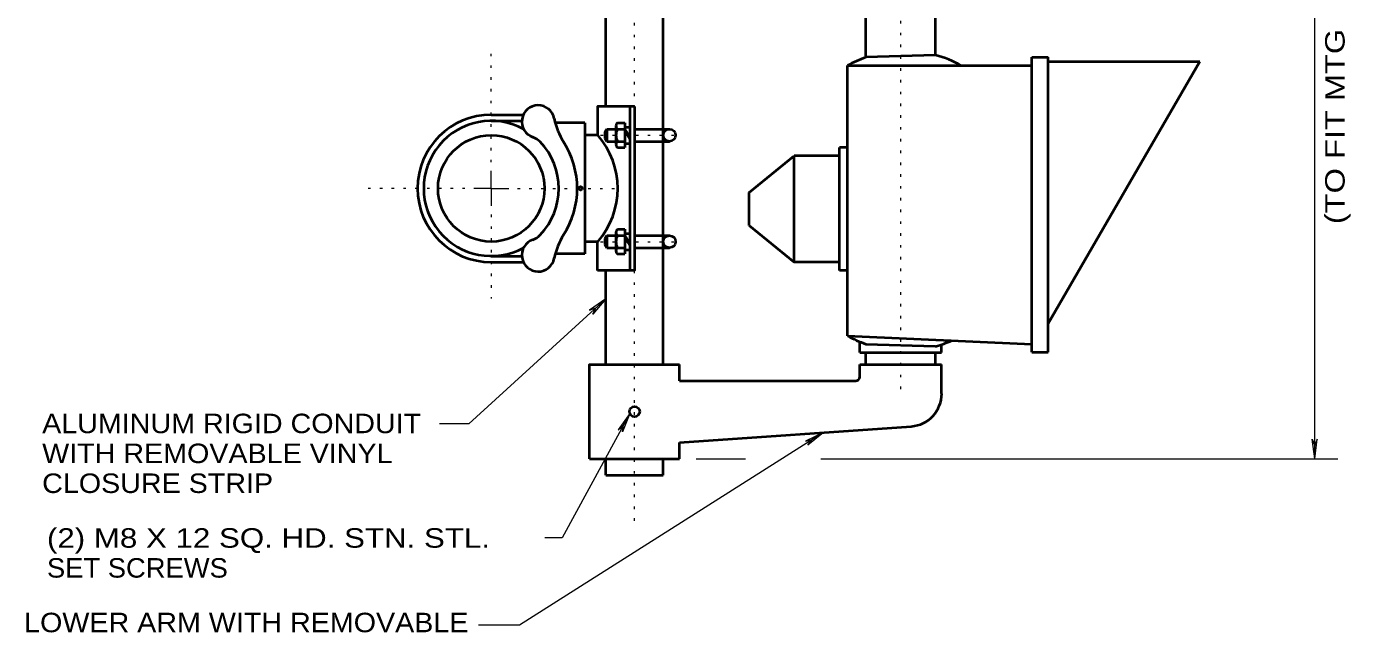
# Model space of a CAD drawing. Extents: x 312583 to 312854, y 144419 to 144597.
# Drawn here: x 312717.4 to 312769, y 144455.6 to 144479.3 of the extents above; entities that cross this region are included whole.
import ezdxf

# ---------------------------------------------------------------- set-up
doc = ezdxf.new("R2010")
doc.units = 0
doc.header["$LTSCALE"] = 0.3
doc.linetypes.add('DOTTED', pattern=[1.5, 0.3, -1.2])
doc.layers.add('1', color=7, linetype='Continuous', lineweight=40)
doc.layers.add('2', color=7, linetype='Continuous', lineweight=40)

msp = doc.modelspace()

# ---------------------------------------------------------------- linework, layer by layer
at = {"layer": '1', "linetype": 'DOTTED', "lineweight": 13}
for p, q in [((312741.0994, 144459.9829), (312741.0994, 144511.0659)), ((312751.4801, 144465.1195), (312751.4801, 144507.1559)), ((312739.7731, 144475.0249), (312742.9854, 144475.0249)), ((312739.7731, 144470.8695), (312742.8858, 144470.8695))]:
    msp.add_line(p, q, dxfattribs=at)
at = {"layer": '1'}
for p, q in [((312742.2188, 144466.0779), (312742.2188, 144506.0059)), ((312739.9801, 144476.1442), (312739.9801, 144486.0419)), ((312750.1231, 144478.0609), (312750.1231, 144480.1845)), ((312752.8371, 144478.1452), (312752.8371, 144480.1002)), ((312752.8371, 144478.1452), (312750.1231, 144478.0609)), ((312756.5938, 144466.5609), (312756.5938, 144478.0609)), ((312756.5938, 144478.0609), (312757.2301, 144478.0609)), ((312757.2301, 144466.5609), (312757.2301, 144478.0609)), ((312757.2301, 144477.8999), (312763.1411, 144477.8999)), ((312757.2301, 144467.6725), (312763.1411, 144477.8999)), ((312749.4024, 144477.7389), (312756.5938, 144477.7389)), ((312749.4024, 144467.1972), (312749.4024, 144477.7389)), ((312735.5104, 144475.8222), (312736.7601, 144475.8222)), ((312735.5104, 144475.5845), (312736.6988, 144475.5845)), ((312739.1521, 144475.5002), (312738.0021, 144475.5002)), ((312739.1521, 144475.5002), (312739.1521, 144470.3942)), ((312740.3711, 144475.3852), (312740.3711, 144474.6569)), ((312740.4324, 144475.5002), (312740.7238, 144475.5002)), ((312740.7238, 144475.5002), (312740.7238, 144474.5419)), ((312740.7238, 144475.3392), (312740.9078, 144475.3392)), ((312740.9078, 144475.3392), (312740.9078, 144474.7029)), ((312739.6581, 144475.0249), (312739.1521, 144475.0249)), ((312739.9418, 144475.1399), (312740.0108, 144475.2625)), ((312739.9418, 144475.1399), (312739.9418, 144474.9099)), ((312739.9418, 144474.9099), (312740.0108, 144474.7795)), ((312740.0108, 144475.2625), (312740.0108, 144474.7795)), ((312740.0108, 144475.2625), (312740.3711, 144475.2625)), ((312740.4324, 144475.2625), (312740.7238, 144475.2625)), ((312740.7238, 144475.2625), (312740.9078, 144474.9482)), ((312740.7238, 144475.2012), (312740.9078, 144474.8792)), ((312741.0994, 144475.2625), (312742.4564, 144475.2625)), ((312740.0108, 144474.7795), (312740.3711, 144474.7795)), ((312740.4324, 144474.7795), (312740.7238, 144474.7795)), ((312740.4324, 144474.5419), (312740.7238, 144474.5419)), ((312740.7238, 144474.7029), (312740.9078, 144474.7029)), ((312741.0994, 144474.7795), (312742.4564, 144474.7795)), ((312749.0881, 144469.7502), (312749.0881, 144474.5419)), ((312749.4024, 144474.5419), (312749.0881, 144474.5419)), ((312745.5691, 144472.7862), (312747.3248, 144474.2199)), ((312747.3248, 144470.0722), (312747.3248, 144474.2199)), ((312749.0881, 144474.2199), (312747.3248, 144474.2199)), ((312745.5691, 144471.5059), (312745.5691, 144472.7862)), ((312740.3711, 144471.2299), (312740.3711, 144470.5092)), ((312740.4324, 144471.3525), (312740.7238, 144471.3525)), ((312740.7238, 144471.3525), (312740.7238, 144470.3942)), ((312740.7238, 144471.1915), (312740.9078, 144471.1915)), ((312740.9078, 144471.1915), (312740.9078, 144470.5475)), ((312745.5691, 144471.5059), (312747.3248, 144470.0722)), ((312739.6581, 144470.8695), (312739.1521, 144470.8695)), ((312739.6581, 144469.7502), (312739.6581, 144470.8695)), ((312739.9418, 144470.9845), (312740.0108, 144471.1072)), ((312739.9418, 144470.9845), (312739.9418, 144470.7545)), ((312739.9418, 144470.7545), (312740.0108, 144470.6319)), ((312740.0108, 144471.1072), (312740.0108, 144470.6319)), ((312740.0108, 144471.1072), (312740.3711, 144471.1072)), ((312740.4324, 144471.1072), (312740.7238, 144471.1072)), ((312740.7238, 144471.1072), (312740.9078, 144470.7929)), ((312740.7238, 144471.0459), (312740.9078, 144470.7315)), ((312741.0994, 144471.1072), (312742.4564, 144471.1072)), ((312735.5104, 144470.3099), (312736.6988, 144470.3099)), ((312739.1521, 144470.3942), (312738.0021, 144470.3942)), ((312740.0108, 144470.6319), (312740.3711, 144470.6319)), ((312740.4324, 144470.6319), (312740.7238, 144470.6319)), ((312740.4324, 144470.3942), (312740.7238, 144470.3942)), ((312740.7238, 144470.5475), (312740.9078, 144470.5475)), ((312741.0994, 144470.6319), (312742.4564, 144470.6319)), ((312735.5104, 144470.0722), (312736.7601, 144470.0722)), ((312739.9801, 144466.0779), (312739.9801, 144469.7502)), ((312749.0881, 144470.0722), (312747.3248, 144470.0722)), ((312749.4024, 144469.7502), (312749.0881, 144469.7502)), ((312749.4024, 144467.1972), (312756.5938, 144466.8752)), ((312749.8854, 144466.5532), (312749.8854, 144466.9672)), ((312749.8854, 144466.5532), (312753.0748, 144466.5532)), ((312750.1231, 144466.8752), (312752.8371, 144466.7909)), ((312750.1231, 144466.0779), (312750.1231, 144466.5532)), ((312752.8371, 144466.0779), (312752.8371, 144466.5532)), ((312753.0748, 144466.5532), (312753.0748, 144466.8599)), ((312756.5938, 144466.5609), (312757.2301, 144466.5609)), ((312742.8551, 144465.4415), (312742.8551, 144466.0779)), ((312749.8854, 144465.6025), (312749.8854, 144466.0779)), ((312749.8854, 144466.0779), (312753.0748, 144466.0779)), ((312753.0748, 144464.9432), (312753.0748, 144466.0779)), ((312742.8551, 144465.4415), (312749.7244, 144465.4415)), ((312742.8551, 144463.0419), (312751.8864, 144463.6629)), ((312742.8551, 144462.4055), (312742.8551, 144463.0419)), ((312739.3438, 144462.4055), (312742.8551, 144462.4055)), ((312739.9801, 144461.7692), (312739.9801, 144462.4055)), ((312742.2188, 144461.7692), (312742.2188, 144462.4055)), ((312739.9801, 144461.7692), (312742.2188, 144461.7692))]:
    msp.add_line(p, q, dxfattribs=at)
for points in [[(312741.0994, 144476.1442), (312741.0994, 144469.7502), (312739.6581, 144469.7502)], [(312741.0994, 144476.1442), (312739.6581, 144476.1442), (312739.6581, 144475.0249)], [(312741.0994, 144476.1442), (312740.9078, 144476.1442), (312740.9078, 144469.7502)], [(312739.3438, 144462.4055), (312739.3438, 144466.0779), (312742.8551, 144466.0779)]]:
    msp.add_lwpolyline(points, dxfattribs=at)
for centre, radius in [((312735.5079, 144472.9466), 2.0764), ((312742.4558, 144475.023), 0.2396), ((312738.9968, 144472.953), 0.0679), ((312742.4558, 144470.8702), 0.2396), ((312741.0982, 144464.2417), 0.1996)]:
    msp.add_circle(centre, radius, dxfattribs=at)
for centre, radius, start, end in [((312751.6219, 144473.734), 4.5776, 109.12156, 118.98507), ((312751.6219, 144473.734), 4.5776, 61.01507, 74.59737), ((312735.5079, 144472.9466), 2.875, 90, 270), ((312735.5079, 144472.9466), 2.6354, 61.35961, 298.6449), ((312740.4794, 144476.1417), 2.5556, 190.67393, 212.72852), ((312740.5225, 144475.3823), 0.1515, 127.72221, 232.27779), ((312740.8887, 144475.023), 0.5176, 152.42977, 207.57023), ((312735.5079, 144472.9466), 2.6354, 316.47333, 43.52667), ((312735.5079, 144472.9466), 3.3542, 327.27148, 32.72852), ((312740.5225, 144474.6636), 0.1515, 127.72221, 232.27779), ((312740.5225, 144471.2295), 0.1515, 127.72221, 232.27779), ((312740.4794, 144469.7514), 2.5556, 147.27148, 169.32607), ((312740.8887, 144470.8702), 0.5176, 152.42977, 207.57023), ((312740.5225, 144470.5108), 0.1515, 127.72221, 232.27779), ((312751.6219, 144471.2008), 4.5776, 241.01493, 250.87844), ((312751.6219, 144471.2008), 4.5776, 285.40263, 293.90144), ((312749.7232, 144465.5993), 0.1597, 270, 0), ((312751.7995, 144464.9418), 1.2778, 273.94713, 0)]:
    msp.add_arc(centre, radius, start, end, dxfattribs=at)
at = {"layer": '2', "lineweight": 13}
for p, q in [((312767.6261, 144462.4055), (312767.6261, 144509.6859)), ((312735.5104, 144472.9472), (312735.5104, 144473.6295)), ((312735.5104, 144472.9472), (312734.8281, 144472.9472)), ((312735.5104, 144472.9472), (312736.1928, 144472.9472)), ((312735.5104, 144472.9472), (312735.5104, 144472.2649)), ((312739.9801, 144468.6385), (312734.6288, 144463.7625)), ((312739.9801, 144468.6385), (312739.3438, 144468.1939)), ((312739.9801, 144468.6385), (312739.4741, 144468.0482)), ((312739.3438, 144468.1939), (312739.5891, 144468.2859)), ((312739.4741, 144468.0482), (312739.5891, 144468.2859)), ((312740.9154, 144464.1689), (312738.2781, 144459.3235)), ((312740.9154, 144464.1689), (312740.4631, 144463.5325)), ((312740.9154, 144464.1689), (312740.6318, 144463.4482)), ((312734.6288, 144463.7625), (312733.4864, 144463.7625)), ((312748.4671, 144463.4329), (312736.6144, 144455.9195)), ((312740.4631, 144463.5325), (312740.6624, 144463.7089)), ((312740.6318, 144463.4482), (312740.6624, 144463.7089)), ((312748.4671, 144463.4329), (312747.7618, 144463.0955)), ((312748.4671, 144463.4329), (312747.8614, 144462.9345)), ((312747.7618, 144463.0955), (312748.0224, 144463.1492)), ((312747.8614, 144462.9345), (312748.0224, 144463.1492)), ((312767.5264, 144463.1722), (312767.6261, 144462.9269)), ((312767.6261, 144462.4055), (312767.5264, 144463.1722)), ((312767.7181, 144463.1722), (312767.6261, 144462.9269)), ((312767.6261, 144462.4055), (312767.7181, 144463.1722)), ((312743.4991, 144462.4055), (312745.4234, 144462.4055)), ((312748.3598, 144462.4055), (312768.5231, 144462.4055)), ((312738.2781, 144459.3235), (312737.5958, 144459.3235)), ((312736.6144, 144455.9195), (312735.0121, 144455.9195))]:
    msp.add_line(p, q, dxfattribs=at)
at = {"layer": '2', "linetype": 'DOTTED', "lineweight": 13}
for p, q in [((312735.5104, 144473.9669), (312735.5104, 144478.1912)), ((312734.4831, 144472.9472), (312730.5731, 144472.9472)), ((312736.5301, 144472.9472), (312740.4401, 144472.9472)), ((312735.5104, 144471.9275), (312735.5104, 144468.6539))]:
    msp.add_line(p, q, dxfattribs=at)
at = {"layer": '2'}
for centre, radius, start, end in [((312737.3402, 144475.55), 0.6389, 10.67393, 250.96957), ((312736.8975, 144474.2666), 0.7188, 43.52836, 70.96956), ((312737.2899, 144472.9466), 3.1515, 318.78748, 41.21252), ((312737.3402, 144470.3431), 0.6389, 109.03043, 349.32607), ((312736.8975, 144471.6265), 0.7188, 289.03044, 316.47164)]:
    msp.add_arc(centre, radius, start, end, dxfattribs=at)

# ---------------------------------------------------------------- texts
at = {"layer": '2', "width": 1.25}
msp.add_text('(TO FIT MTG POSITION & SIGNAL HD. DIMS.)', height=0.76, rotation=90, dxfattribs=at).set_placement((312768.7951, 144471.553))
at = {"layer": '2'}
for s, width, p in [('ALUMINUM RIGID CONDUIT', 1.1, (312717.9921, 144463.4012)), ('WITH REMOVABLE VINYL', 1.1, (312717.9921, 144462.2349)), ('CLOSURE STRIP', 1.1, (312717.9921, 144461.0686)), ('(2) M8 X 12 SQ. HD. STN. STL.', 1.2, (312718.1786, 144458.9338)), ('SET SCREWS', 1.05, (312718.1786, 144457.7675)), ('LOWER ARM WITH REMOVABLE', 1.1, (312717.2884, 144455.6372))]:
    msp.add_text(s, height=0.76, dxfattribs=dict(at, width=width)).set_placement(p)

doc.saveas('drawing.dxf')
